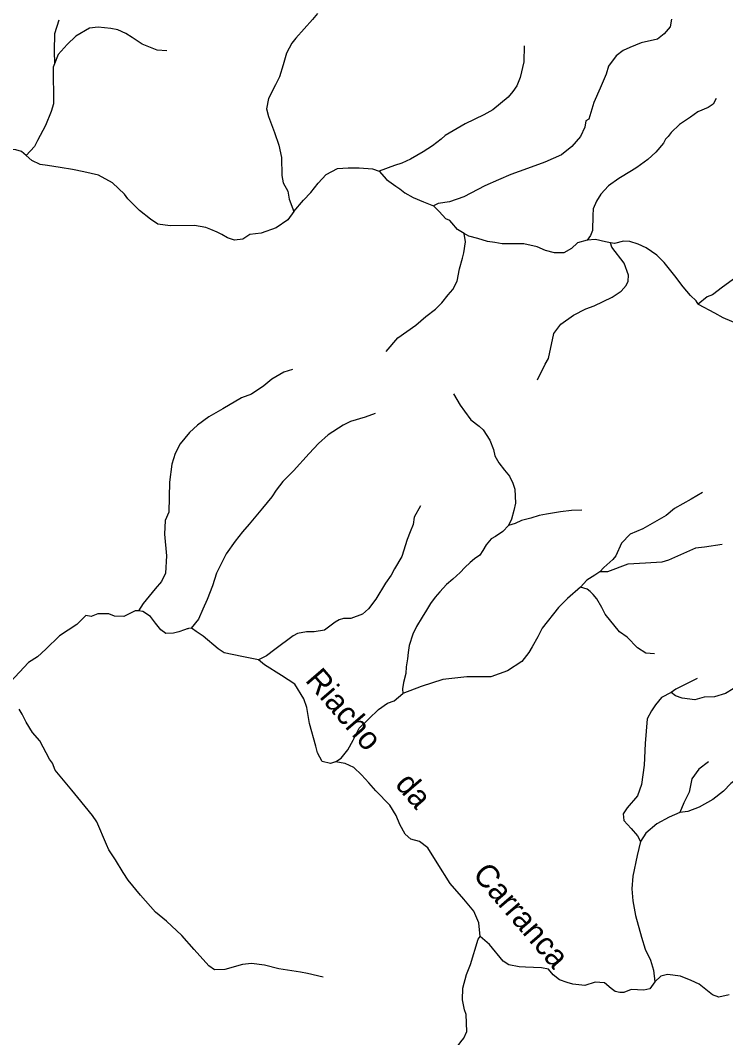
# Model space of a CAD drawing. Extents: x 717.8 to 772.7, y 8672.2 to 8728.
# Drawn here: x 761.18 to 767.35, y 8700.84 to 8709.74 of the extents above; entities that cross this region are included whole.
import ezdxf
from ezdxf.enums import TextEntityAlignment as Align

# ---------------------------------------------------------------- set-up
doc = ezdxf.new("R2010")
doc.units = 0
doc.header["$LTSCALE"] = 0.08
doc.linetypes.add('LONG_DASHED', pattern=[7.5, 6, -1.5])
doc.layers.add('61', color=7, linetype='Continuous')
doc.layers.add('9', color=7, linetype='LONG_DASHED', lineweight=25)

msp = doc.modelspace()

# ---------------------------------------------------------------- linework, layer by layer
at = {"layer": '9'}
for points in [[(763.7794, 8709.8014), (763.7374, 8709.75), (763.6633, 8709.6681), (763.5917, 8709.5876), (763.5546, 8709.5432), (763.5094, 8709.4565), (763.4968, 8709.4142), (763.4806, 8709.3538), (763.4472, 8709.249), (763.4126, 8709.1791), (763.352, 8709.0591), (763.3346, 8708.9696), (763.3497, 8708.9015), (763.4045, 8708.7614), (763.4401, 8708.651), (763.4657, 8708.543), (763.4683, 8708.3835), (763.4804, 8708.3199), (763.5214, 8708.247), (763.533, 8708.1788), (763.5717, 8708.0689)], [(761.515, 8709.7445), (761.4784, 8709.6238), (761.4742, 8709.4745), (761.4784, 8709.3622)], [(762.4609, 8709.4766), (762.3754, 8709.4824), (762.2459, 8709.5331), (762.159, 8709.5934), (762.1027, 8709.6265), (762.0316, 8709.6582), (761.9718, 8709.6716), (761.8603, 8709.6834), (761.7836, 8709.6741), (761.6649, 8709.6047), (761.5885, 8709.5315), (761.5087, 8709.4424), (761.4784, 8709.3622)], [(766.8771, 8709.753), (766.8667, 8709.6848), (766.8136, 8709.6248), (766.7551, 8709.5789), (766.6121, 8709.5448), (766.5123, 8709.5048), (766.456, 8709.4789), (766.3953, 8709.4307), (766.3271, 8709.3411), (766.3052, 8709.2712), (766.2549, 8709.1487), (766.1999, 8709.0231), (766.1555, 8708.8763), (766.1277, 8708.8639), (766.1184, 8708.8089), (766.0814, 8708.7274), (766.0074, 8708.6384), (765.9155, 8708.5665), (765.7696, 8708.502), (765.6187, 8708.445), (765.4733, 8708.3939), (765.363, 8708.3472), (765.2441, 8708.2944), (765.0605, 8708.1975), (764.936, 8708.1531), (764.8368, 8708.1412), (764.7949, 8708.1195)], [(765.589, 8709.5198), (765.5852, 8709.3806), (765.555, 8709.2434), (765.5233, 8709.1706), (765.4907, 8709.1202), (765.4481, 8709.0699), (765.316, 8708.9587), (765.2368, 8708.9155), (765.0712, 8708.8366), (764.8966, 8708.7343), (764.8618, 8708.7041), (764.7879, 8708.6456), (764.7061, 8708.5909), (764.5938, 8708.5274), (764.517, 8708.4939), (764.4544, 8708.4721), (764.3193, 8708.4239)], [(761.4784, 8709.3622), (761.4669, 8709.3324), (761.4701, 8709.0108), (761.4491, 8708.9452), (761.3989, 8708.8231), (761.3299, 8708.6916), (761.3036, 8708.6382), (761.2315, 8708.5608)], [(767.2706, 8709.0583), (767.2422, 8709.0091), (767.1987, 8708.979), (767.1076, 8708.9414), (767.0453, 8708.8953), (766.9485, 8708.8297), (766.875, 8708.7611), (766.85, 8708.7257), (766.826, 8708.7029), (766.8085, 8708.668), (766.7416, 8708.5878), (766.671, 8708.5238), (766.5746, 8708.4561), (766.5278, 8708.4269), (766.4176, 8708.3592), (766.3267, 8708.2949), (766.2586, 8708.2218), (766.2224, 8708.1607), (766.1933, 8708.0921), (766.1898, 8708.036), (766.188, 8707.9022), (766.1701, 8707.8585), (766.1394, 8707.8202)], [(761.2315, 8708.5608), (761.1902, 8708.5937), (761.1387, 8708.6094), (761.0247, 8708.6164), (760.9473, 8708.6474), (760.8273, 8708.7249), (760.7197, 8708.7443), (760.6293, 8708.7801), (760.53, 8708.8055), (760.2945, 8708.8016), (760.2395, 8708.7675), (760.1458, 8708.6838), (760.0216, 8708.6306), (759.9168, 8708.5917), (759.8466, 8708.5562)], [(763.5717, 8708.0689), (763.5213, 8707.9979), (763.4172, 8707.9275), (763.2867, 8707.8805), (763.1876, 8707.8681), (763.1256, 8707.8278), (763.0546, 8707.8197), (762.991, 8707.8394), (762.9413, 8707.8675), (762.9019, 8707.8887), (762.8463, 8707.9133), (762.8028, 8707.9285), (762.7037, 8707.9471), (762.4894, 8707.9448), (762.3823, 8707.9579), (762.3184, 8708.0026), (762.222, 8708.0795), (762.1199, 8708.1807), (762.0896, 8708.2207), (761.9858, 8708.3207), (761.8627, 8708.3866), (761.7334, 8708.4171), (761.6342, 8708.4383), (761.5276, 8708.4561), (761.4154, 8708.4711), (761.3527, 8708.4802), (761.2789, 8708.5147), (761.2315, 8708.5608)], [(763.5717, 8708.0689), (763.6564, 8708.1678), (763.7204, 8708.2354), (763.7847, 8708.3175), (763.8551, 8708.395), (763.9558, 8708.4469), (764.0495, 8708.4523), (764.144, 8708.4531), (764.2602, 8708.4446), (764.3193, 8708.4239)], [(764.3193, 8708.4239), (764.3841, 8708.3501), (764.4654, 8708.2912), (764.4992, 8708.2678), (764.5445, 8708.2343), (764.6161, 8708.1913), (764.7067, 8708.153), (764.7949, 8708.1195)], [(765.0649, 8707.8766), (765.0057, 8707.9116), (764.9546, 8707.9714), (764.9388, 8707.991), (764.9019, 8708.0059), (764.8457, 8708.0693), (764.7949, 8708.1195)], [(764.3808, 8706.8451), (764.4824, 8706.9653), (764.6401, 8707.0763), (764.7273, 8707.1518), (764.8137, 8707.2164), (764.8683, 8707.2698), (764.9224, 8707.3402), (764.9632, 8707.3876), (765.0011, 8707.4605), (765.0227, 8707.5683), (765.0488, 8707.6608), (765.0601, 8707.7086), (765.0749, 8707.803), (765.0649, 8707.8766)], [(766.1394, 8707.8202), (766.055, 8707.796), (766.0035, 8707.745), (765.9346, 8707.708), (765.8557, 8707.7084), (765.7763, 8707.728), (765.7017, 8707.7603), (765.586, 8707.7862), (765.3957, 8707.7882), (765.3327, 8707.7973), (765.2687, 8707.8086), (765.1844, 8707.8339), (765.105, 8707.8547), (765.0649, 8707.8766)], [(766.3438, 8707.7952), (766.3002, 8707.8031), (766.2137, 8707.8247), (766.1394, 8707.8202)], [(767.1119, 8707.2603), (767.0952, 8707.2877), (767.0457, 8707.3343), (766.9793, 8707.4099), (766.9079, 8707.5063), (766.814, 8707.6231), (766.7487, 8707.6891), (766.6561, 8707.7506), (766.5854, 8707.7842), (766.5127, 8707.8087), (766.4574, 8707.8092), (766.3796, 8707.7887), (766.3438, 8707.7952)], [(765.7054, 8706.5965), (765.7738, 8706.7329), (765.8009, 8706.7836), (765.8483, 8707.003), (765.911, 8707.0849), (766.0192, 8707.1639), (766.1275, 8707.217), (766.202, 8707.2435), (766.2805, 8707.2838), (766.3582, 8707.3208), (766.4377, 8707.3722), (766.481, 8707.4225), (766.4978, 8707.4609), (766.5008, 8707.5133), (766.4642, 8707.6192), (766.3553, 8707.7585), (766.3438, 8707.7952)], [(767.4419, 8707.4931), (767.3239, 8707.4081), (767.2378, 8707.341), (767.1907, 8707.3227), (767.1119, 8707.2603)], [(767.1119, 8707.2603), (767.2556, 8707.1829), (767.3288, 8707.1418), (767.5008, 8707.0682), (767.6009, 8707.0406), (767.684, 8706.9984), (767.7659, 8706.9336)], [(763.5609, 8706.6878), (763.4851, 8706.6629), (763.3791, 8706.6026), (763.3096, 8706.5434), (763.2015, 8706.4717), (763.1153, 8706.4395), (762.9513, 8706.3419), (762.8287, 8706.2744), (762.7301, 8706.2016), (762.6605, 8706.1372), (762.5785, 8706.0374), (762.5328, 8705.9512), (762.5037, 8705.8577), (762.484, 8705.7008), (762.4788, 8705.44), (762.4467, 8705.3663), (762.4405, 8705.2479), (762.4592, 8705.0557), (762.4508, 8704.905), (762.4138, 8704.8313), (762.3577, 8704.7684), (762.2543, 8704.6394), (762.2137, 8704.5766)], [(764.9704, 8706.4746), (765.0296, 8706.3765), (765.0656, 8706.3232), (765.1229, 8706.248), (765.1964, 8706.1911), (765.2312, 8706.1584), (765.2885, 8706.0687), (765.3214, 8705.9883), (765.3322, 8705.9315), (765.3663, 8705.8705), (765.4165, 8705.8059), (765.4601, 8705.7555), (765.4889, 8705.6933), (765.5076, 8705.6404), (765.5121, 8705.5189), (765.4972, 8705.4541), (765.4775, 8705.3776), (765.4522, 8705.3228)], [(764.2841, 8706.3037), (764.1977, 8706.2716), (764.0674, 8706.2328), (764.0049, 8706.2017), (763.8734, 8706.1161), (763.7886, 8706.0385), (763.7063, 8705.9526), (763.5712, 8705.8015), (763.4769, 8705.7063), (763.4191, 8705.6306), (763.3792, 8705.5729), (763.2974, 8705.4727), (763.1812, 8705.3344), (763.1222, 8705.2659), (763.0588, 8705.1858), (762.9817, 8705.0738), (762.8974, 8704.9058), (762.8623, 8704.7937), (762.8132, 8704.6747), (762.7754, 8704.5894), (762.7391, 8704.5032), (762.6729, 8704.4256)], [(767.1497, 8705.6122), (767.0516, 8705.5537), (766.9052, 8705.4713), (766.8303, 8705.4105), (766.6286, 8705.2928), (766.5171, 8705.2453), (766.4397, 8705.1683), (766.3904, 8705.0556), (766.3645, 8705.0257), (766.2868, 8704.9542), (766.2514, 8704.9171)], [(764.6828, 8705.4959), (764.6248, 8705.3949), (764.6159, 8705.3315), (764.5908, 8705.2672), (764.5641, 8705.2002), (764.5194, 8705.0519), (764.4533, 8704.9436), (764.4248, 8704.8882), (764.3756, 8704.8167), (764.2917, 8704.6782), (764.2274, 8704.5942), (764.1747, 8704.5469), (764.0703, 8704.5098), (764.0086, 8704.5089), (763.9702, 8704.4982), (763.9356, 8704.4755), (763.8425, 8704.4071), (763.7514, 8704.3928), (763.6831, 8704.3918), (763.606, 8704.3778), (763.5683, 8704.3568), (763.4066, 8704.238), (763.3343, 8704.1808), (763.2623, 8704.1471)], [(766.0946, 8705.456), (766.0031, 8705.4542), (765.9062, 8705.4422), (765.783, 8705.4227), (765.721, 8705.4109), (765.6469, 8705.387), (765.5653, 8705.3675), (765.5091, 8705.34), (765.4522, 8705.3228)], [(765.4522, 8705.3228), (765.4015, 8705.2699), (765.3387, 8705.2264), (765.2992, 8705.2048), (765.2561, 8705.154), (765.2273, 8705.1029), (765.2017, 8705.0641), (765.1532, 8705.0306), (765.1167, 8704.9977), (765.0683, 8704.9564), (765.0288, 8704.9104), (764.9649, 8704.8517), (764.9086, 8704.8068), (764.8502, 8704.7409), (764.8097, 8704.6957), (764.7699, 8704.6405), (764.7334, 8704.5812), (764.6951, 8704.5193), (764.6473, 8704.4383), (764.6138, 8704.3725), (764.5815, 8704.272), (764.5737, 8704.2116), (764.5691, 8704.1561), (764.5572, 8704.087), (764.5517, 8704.0261), (764.5338, 8703.9495), (764.5247, 8703.8927), (764.5259, 8703.8528)], [(767.3206, 8705.1557), (767.1682, 8705.1332), (767.0873, 8705.123), (766.853, 8705.0186), (766.7947, 8705.0002), (766.6517, 8704.9931), (766.4963, 8704.9841), (766.3181, 8704.9176), (766.2514, 8704.9171)], [(766.2514, 8704.9171), (766.2076, 8704.8881), (766.1375, 8704.8448), (766.0811, 8704.7831)], [(766.0811, 8704.7831), (765.9686, 8704.685), (765.8884, 8704.6064), (765.7455, 8704.4241), (765.7085, 8704.3489), (765.6597, 8704.2615), (765.6285, 8704.2106), (765.5679, 8704.1318), (765.4436, 8704.0515), (765.2972, 8703.9979), (765.0883, 8703.9979), (764.8774, 8703.9738), (764.6863, 8703.914), (764.5259, 8703.8528)], [(766.7306, 8704.2003), (766.6529, 8704.2057), (766.5814, 8704.253), (766.4895, 8704.3468), (766.4243, 8704.3933), (766.2974, 8704.5458), (766.2679, 8704.6057), (766.2259, 8704.6799), (766.1929, 8704.7192), (766.1679, 8704.746), (766.1411, 8704.7656), (766.0811, 8704.7831)], [(762.2137, 8704.5766), (762.1827, 8704.5767), (762.0839, 8704.5251), (762.0033, 8704.5279), (761.9541, 8704.5495), (761.8948, 8704.5503), (761.8585, 8704.5483), (761.7993, 8704.5264), (761.7527, 8704.5354), (761.6721, 8704.4575), (761.5225, 8704.3557), (761.4016, 8704.2394), (761.3307, 8704.1735), (761.2512, 8704.1248), (761.0154, 8703.8709)], [(762.6729, 8704.4256), (762.6506, 8704.4211), (762.6444, 8704.4188), (762.6393, 8704.4176), (762.6154, 8704.4105), (762.5662, 8704.3926), (762.5185, 8704.3792), (762.4519, 8704.3774), (762.4091, 8704.4105), (762.3608, 8704.4686), (762.318, 8704.5249), (762.2501, 8704.5704), (762.2137, 8704.5766)], [(763.2623, 8704.1471), (763.1164, 8704.1763), (762.9619, 8704.2094), (762.9119, 8704.2442), (762.779, 8704.3555), (762.7175, 8704.3961), (762.6864, 8704.4179), (762.6729, 8704.4256)], [(763.9366, 8703.2535), (763.8951, 8703.239), (763.8222, 8703.2568), (763.779, 8703.3337), (763.7656, 8703.3918), (763.7102, 8703.5901), (763.6852, 8703.7313), (763.6602, 8703.8063), (763.5816, 8703.9332), (763.4643, 8704.0113), (763.3147, 8704.1039), (763.2623, 8704.1471)], [(767.6154, 8704.1247), (767.5289, 8704.0419), (767.5031, 8703.9927), (767.4651, 8703.9324), (767.419, 8703.8931), (767.3517, 8703.8518), (767.256, 8703.8247), (767.1629, 8703.82), (767.084, 8703.7962), (766.9728, 8703.813), (766.9134, 8703.8324), (766.8748, 8703.8617)], [(767.1021, 8703.9837), (766.917, 8703.8897), (766.8748, 8703.8617)], [(763.9366, 8703.2535), (763.9871, 8703.2877), (764.0451, 8703.3583), (764.0916, 8703.4451), (764.1457, 8703.5506), (764.313, 8703.712), (764.3926, 8703.7682), (764.45, 8703.7892), (764.5259, 8703.8528)], [(766.8748, 8703.8617), (766.7918, 8703.8169), (766.7375, 8703.7548), (766.7039, 8703.7005), (766.6651, 8703.632), (766.6465, 8703.4155), (766.6387, 8703.2267), (766.6152, 8703.0561), (766.5802, 8702.958), (766.4889, 8702.8528), (766.4555, 8702.7992), (766.462, 8702.741), (766.5267, 8702.6712), (766.5805, 8702.6077), (766.6084, 8702.5581)], [(763.8299, 8701.3695), (763.693, 8701.4033), (763.6321, 8701.4143), (763.4413, 8701.443), (763.3154, 8701.4768), (763.2031, 8701.4895), (763.1226, 8701.4812), (762.969, 8701.4365), (762.8794, 8701.4357), (762.8287, 8701.4686), (762.7012, 8701.6123), (762.5922, 8701.7339), (762.4586, 8701.8607), (762.3624, 8701.9401), (762.2297, 8702.0879), (762.1233, 8702.2181), (762.0802, 8702.2865), (762.0134, 8702.3964), (761.9526, 8702.4851), (761.9323, 8702.5324), (761.8495, 8702.7285), (761.8092, 8702.7849), (761.6833, 8702.9426), (761.6308, 8703.0057), (761.4843, 8703.1813), (761.4611, 8703.2428), (761.4341, 8703.2788), (761.3499, 8703.4391), (761.2864, 8703.5118), (761.2291, 8703.6005), (761.1962, 8703.6715), (761.169, 8703.7168)], [(768.1393, 8703.5465), (768.0876, 8703.4634), (768.0217, 8703.4014), (767.9092, 8703.3587), (767.7894, 8703.3051), (767.6478, 8703.2468), (767.5479, 8703.1802), (767.3979, 8703.0637), (767.3341, 8702.9977), (767.2403, 8702.926), (767.1201, 8702.8587), (767.0218, 8702.8212), (766.9527, 8702.8112)], [(765.2041, 8701.7251), (765.1911, 8701.8467), (765.1486, 8701.9478), (765.0613, 8702.0537), (764.9405, 8702.1895), (764.8281, 8702.3722), (764.7445, 8702.5007), (764.6736, 8702.5564), (764.5959, 8702.5784), (764.5477, 8702.6206), (764.5014, 8702.7052), (764.4691, 8702.7853), (764.4117, 8702.8768), (764.2915, 8702.9995), (764.2306, 8703.0695), (764.1654, 8703.1407), (764.0985, 8703.2059), (764.0225, 8703.2406), (763.9366, 8703.2535)], [(767.2036, 8703.2537), (767.1169, 8703.1904), (767.0562, 8703.1063), (767.0316, 8702.9899), (766.9864, 8702.8968), (766.9527, 8702.8112)], [(766.9527, 8702.8112), (766.8571, 8702.7713), (766.7511, 8702.7119), (766.6525, 8702.6314), (766.6084, 8702.5581)], [(766.6084, 8702.5581), (766.5773, 8702.4339), (766.539, 8702.2541), (766.5299, 8702.1442), (766.541, 8702.0389), (766.5638, 8701.911), (766.615, 8701.7195), (766.648, 8701.6149), (766.695, 8701.5181), (766.7198, 8701.4304), (766.7324, 8701.3304)], [(764.9492, 8700.6283), (764.9568, 8700.6836), (764.9933, 8700.7489), (765.0358, 8700.8045), (765.0603, 8700.8374), (765.0866, 8700.8944), (765.0806, 8701.0439), (765.067, 8701.0857), (765.0496, 8701.173), (765.0526, 8701.2747), (765.0843, 8701.3926), (765.1202, 8701.4825), (765.1866, 8701.7016), (765.2041, 8701.7251)], [(766.7324, 8701.3304), (766.6897, 8701.2688), (766.6366, 8701.258), (766.524, 8701.262), (766.4618, 8701.2367), (766.4252, 8701.2359), (766.3857, 8701.2464), (766.3508, 8701.2699), (766.2932, 8701.32), (766.209, 8701.3263), (766.1212, 8701.2984), (766.0139, 8701.3086), (765.9645, 8701.3242), (765.8985, 8701.3469), (765.8426, 8701.391), (765.8018, 8701.4402), (765.7403, 8701.452), (765.6014, 8701.4589), (765.5464, 8701.46), (765.4542, 8701.4783), (765.4043, 8701.5092), (765.2861, 8701.6574), (765.2041, 8701.7251)], [(767.3842, 8701.217), (767.2923, 8701.1967), (767.2377, 8701.2161), (767.1192, 8701.3095), (767.0512, 8701.3423), (766.9566, 8701.3795), (766.8435, 8701.3938), (766.7837, 8701.3787), (766.7324, 8701.3304)]]:
    msp.add_lwpolyline(points, dxfattribs=at)

# ---------------------------------------------------------------- texts
at = {"layer": '61'}
msp.add_text('Riacho     da          Carranca', height=0.2, rotation=310.736, dxfattribs=at).set_placement((764.7565, 8702.6983), align=Align.CENTER)

doc.saveas('drawing.dxf')
